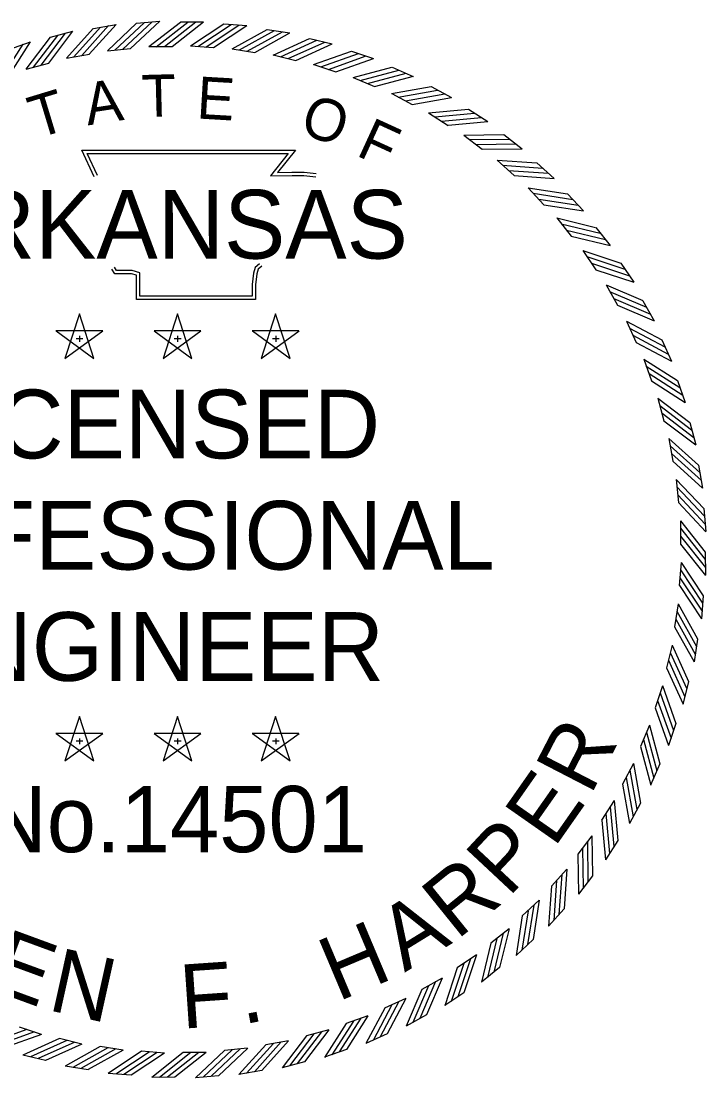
# Model space of a CAD drawing. Extents: x 16 to 1228740, y 11 to 152440.
# Drawn here: x 17.7457 to 17.8572, y 10.8174 to 10.9896 of the extents above; entities that cross this region are included whole.
import ezdxf

# ---------------------------------------------------------------- set-up
doc = ezdxf.new("R2010")
doc.units = 0
doc.layers.add('STAMP_FRED', color=7, linetype='Continuous')

msp = doc.modelspace()

# ---------------------------------------------------------------- linework, layer by layer
at = {"layer": 'STAMP_FRED'}
for p, q in [((17.7645, 10.98923), (17.76826, 10.98957)), ((17.77164, 10.98944), (17.77541, 10.98944)), ((17.75049, 10.98696), (17.75413, 10.98792)), ((17.75745, 10.98838), (17.76116, 10.98904)), ((17.7787, 10.98916), (17.78246, 10.98888)), ((17.78575, 10.98824), (17.78947, 10.98765)), ((17.74366, 10.98497), (17.74722, 10.98623)), ((17.7927, 10.98675), (17.79636, 10.98586)), ((17.75975, 10.98476), (17.76351, 10.98511)), ((17.7665, 10.98543), (17.77028, 10.98543)), ((17.77328, 10.98553), (17.77705, 10.98526)), ((17.78004, 10.98508), (17.78378, 10.98449)), ((17.7995, 10.98468), (17.80308, 10.98349)), ((17.74653, 10.98177), (17.75018, 10.98274)), ((17.75308, 10.98354), (17.7568, 10.9842)), ((17.78675, 10.98407), (17.79042, 10.98317)), ((17.79335, 10.9825), (17.79694, 10.98131)), ((17.80611, 10.98207), (17.80957, 10.98058)), ((17.7998, 10.9804), (17.80327, 10.97892)), ((17.80605, 10.97778), (17.80939, 10.97601)), ((17.81247, 10.97891), (17.81581, 10.97715)), ((17.81206, 10.97464), (17.81525, 10.9726)), ((17.81856, 10.97525), (17.82173, 10.97321)), ((17.8178, 10.97102), (17.8208, 10.96873)), ((17.82432, 10.97109), (17.82732, 10.9688)), ((17.82321, 10.96694), (17.82602, 10.96441)), ((17.82972, 10.96647), (17.83252, 10.96394)), ((17.82827, 10.96242), (17.83086, 10.95967)), ((17.83472, 10.96142), (17.8373, 10.95867)), ((17.83295, 10.95751), (17.83529, 10.95455)), ((17.83929, 10.95597), (17.84163, 10.95302)), ((17.83719, 10.95222), (17.83929, 10.94908)), ((17.84338, 10.95017), (17.84548, 10.94703)), ((17.84099, 10.9466), (17.84282, 10.9433)), ((17.84699, 10.94404), (17.84882, 10.94074)), ((17.75517, 10.94187), (17.75281, 10.93464)), ((17.75752, 10.93464), (17.75517, 10.94188)), ((17.77116, 10.94187), (17.7688, 10.93464)), ((17.77351, 10.93464), (17.77116, 10.94188)), ((17.78715, 10.94187), (17.78479, 10.93464)), ((17.7895, 10.93464), (17.78715, 10.94188)), ((17.84431, 10.94069), (17.84586, 10.93724)), ((17.75897, 10.93911), (17.75136, 10.93912)), ((17.75137, 10.93911), (17.75752, 10.93463)), ((17.75282, 10.93464), (17.75898, 10.93911)), ((17.75463, 10.9379), (17.75576, 10.9379)), ((17.75518, 10.9383), (17.75518, 10.93735)), ((17.77496, 10.93911), (17.76735, 10.93912)), ((17.76736, 10.93911), (17.77351, 10.93463)), ((17.76881, 10.93464), (17.77497, 10.93911)), ((17.77062, 10.9379), (17.77175, 10.9379)), ((17.77117, 10.9383), (17.77117, 10.93735)), ((17.79095, 10.93911), (17.78334, 10.93912)), ((17.78335, 10.93911), (17.7895, 10.93463)), ((17.7848, 10.93464), (17.79096, 10.93911)), ((17.78661, 10.9379), (17.78774, 10.9379)), ((17.78716, 10.9383), (17.78716, 10.93735)), ((17.85008, 10.93764), (17.85163, 10.9342)), ((17.84713, 10.93452), (17.84839, 10.93096)), ((17.85263, 10.93101), (17.85389, 10.92745)), ((17.84943, 10.92814), (17.85039, 10.92449)), ((17.85462, 10.92419), (17.85558, 10.92054)), ((17.8512, 10.9216), (17.85186, 10.91787)), ((17.85604, 10.91723), (17.8567, 10.91351)), ((17.85242, 10.91492), (17.85277, 10.91116)), ((17.85689, 10.91017), (17.85723, 10.90642)), ((17.85309, 10.90818), (17.85312, 10.9044)), ((17.85714, 10.90307), (17.85718, 10.8993)), ((17.85319, 10.90139), (17.85291, 10.89763)), ((17.85682, 10.89597), (17.85654, 10.89221)), ((17.85274, 10.89463), (17.85215, 10.8909)), ((17.85173, 10.88792), (17.85083, 10.88425)), ((17.8559, 10.88892), (17.85531, 10.8852)), ((17.85016, 10.88132), (17.84897, 10.87774)), ((17.85441, 10.88197), (17.85351, 10.87831)), ((17.75517, 10.87631), (17.75281, 10.86907)), ((17.75752, 10.86908), (17.75517, 10.87632)), ((17.77116, 10.87631), (17.7688, 10.86907)), ((17.77351, 10.86908), (17.77116, 10.87632)), ((17.78715, 10.87631), (17.78479, 10.86907)), ((17.7895, 10.86908), (17.78715, 10.87632)), ((17.84806, 10.87488), (17.84658, 10.8714)), ((17.85234, 10.87517), (17.85115, 10.8716)), ((17.75897, 10.87355), (17.75136, 10.87355)), ((17.75137, 10.87355), (17.75752, 10.86907)), ((17.75282, 10.86908), (17.75898, 10.87355)), ((17.75518, 10.87274), (17.75518, 10.87178)), ((17.77496, 10.87355), (17.76735, 10.87355)), ((17.76736, 10.87355), (17.77351, 10.86907)), ((17.76881, 10.86908), (17.77497, 10.87355)), ((17.77117, 10.87274), (17.77117, 10.87178)), ((17.79095, 10.87355), (17.78334, 10.87355)), ((17.78335, 10.87355), (17.7895, 10.86907)), ((17.7848, 10.86908), (17.79096, 10.87355)), ((17.78716, 10.87274), (17.78716, 10.87178)), ((17.75463, 10.87233), (17.75576, 10.87233)), ((17.77062, 10.87233), (17.77175, 10.87233)), ((17.78661, 10.87233), (17.78774, 10.87233)), ((17.84543, 10.86862), (17.84367, 10.86528)), ((17.84973, 10.86857), (17.84824, 10.8651)), ((17.8423, 10.86261), (17.84026, 10.85943)), ((17.84657, 10.8622), (17.84481, 10.85887)), ((17.83868, 10.85687), (17.83639, 10.85387)), ((17.8429, 10.85611), (17.84087, 10.85294)), ((17.8346, 10.85146), (17.83207, 10.84866)), ((17.83875, 10.85035), (17.83646, 10.84736)), ((17.83008, 10.8464), (17.82733, 10.84381)), ((17.83413, 10.84495), (17.8316, 10.84216)), ((17.82517, 10.84173), (17.82221, 10.83938)), ((17.82908, 10.83995), (17.82633, 10.83737)), ((17.81988, 10.83748), (17.81674, 10.83538)), ((17.82363, 10.83539), (17.82068, 10.83305)), ((17.81426, 10.83368), (17.81096, 10.83185)), ((17.81782, 10.83129), (17.81469, 10.8292)), ((17.80835, 10.83036), (17.8049, 10.82881)), ((17.8117, 10.82768), (17.8084, 10.82586)), ((17.80218, 10.82754), (17.79862, 10.82628)), ((17.74898, 10.82451), (17.7454, 10.8257)), ((17.7958, 10.82524), (17.79215, 10.82428)), ((17.8053, 10.82459), (17.80186, 10.82305)), ((17.75558, 10.82295), (17.75191, 10.82384)), ((17.76229, 10.82194), (17.75856, 10.82252)), ((17.78925, 10.82347), (17.78553, 10.82282)), ((17.74963, 10.82027), (17.74597, 10.82116)), ((17.76905, 10.82148), (17.76529, 10.82176)), ((17.77583, 10.82159), (17.77206, 10.82155)), ((17.78258, 10.82225), (17.77882, 10.82191)), ((17.79867, 10.82204), (17.79511, 10.82079)), ((17.75658, 10.81877), (17.75286, 10.81936)), ((17.79185, 10.82005), (17.7882, 10.81909)), ((17.76363, 10.81786), (17.75987, 10.81813)), ((17.77073, 10.81753), (17.76696, 10.81749)), ((17.77783, 10.81779), (17.77408, 10.81744)), ((17.78489, 10.81863), (17.78117, 10.81797))]:
    msp.add_line(p, q, dxfattribs=at)
for points in [[(17.76226, 10.98501), (17.76701, 10.98947)], [(17.76351, 10.98511), (17.76826, 10.98958)], [(17.76649, 10.98542), (17.77164, 10.98943)], [(17.76771, 10.98541), (17.77285, 10.98942)], [(17.76902, 10.98544), (17.77416, 10.98945)], [(17.77027, 10.98543), (17.77542, 10.98944)], [(17.75018, 10.98274), (17.75413, 10.98792)], [(17.75307, 10.98354), (17.75744, 10.98838)], [(17.75427, 10.98374), (17.75864, 10.98858)], [(17.75556, 10.98399), (17.75992, 10.98884)], [(17.75679, 10.9842), (17.76116, 10.98904)], [(17.75974, 10.98476), (17.7645, 10.98922)], [(17.76095, 10.98486), (17.76571, 10.98932)], [(17.77327, 10.98553), (17.7787, 10.98915)], [(17.77448, 10.98543), (17.77991, 10.98905)], [(17.77579, 10.98536), (17.78122, 10.98898)], [(17.77704, 10.98526), (17.78247, 10.98888)], [(17.78004, 10.98508), (17.78574, 10.98824)], [(17.78124, 10.98488), (17.78694, 10.98804)], [(17.78253, 10.9847), (17.78824, 10.98786)], [(17.74371, 10.98073), (17.74722, 10.98623)], [(17.74653, 10.98177), (17.75048, 10.98696)], [(17.7477, 10.98207), (17.75166, 10.98726)], [(17.74896, 10.98243), (17.75292, 10.98762)], [(17.78377, 10.98449), (17.78948, 10.98766)], [(17.78675, 10.98406), (17.79269, 10.98674)], [(17.78792, 10.98377), (17.79387, 10.98645)], [(17.7892, 10.98348), (17.79515, 10.98617)], [(17.74252, 10.98033), (17.74603, 10.98582)], [(17.79042, 10.98318), (17.79636, 10.98586)], [(17.79334, 10.9825), (17.79949, 10.98468)], [(17.79449, 10.98211), (17.80064, 10.98429)], [(17.79574, 10.98172), (17.80189, 10.9839)], [(17.79693, 10.98131), (17.80308, 10.98349)], [(17.79979, 10.9804), (17.8061, 10.98207)], [(17.8009, 10.97991), (17.80721, 10.98158)], [(17.80212, 10.97942), (17.80843, 10.98109)], [(17.80327, 10.97892), (17.80958, 10.98059)], [(17.80604, 10.97777), (17.81247, 10.97891)], [(17.80711, 10.9772), (17.81353, 10.97834)], [(17.80828, 10.97661), (17.81471, 10.97775)], [(17.80939, 10.97601), (17.81581, 10.97715)], [(17.81206, 10.97464), (17.81855, 10.97525)], [(17.81307, 10.97398), (17.81957, 10.97458)], [(17.81419, 10.97329), (17.82069, 10.9739)], [(17.81524, 10.97261), (17.82174, 10.97321)], [(17.81779, 10.97102), (17.82432, 10.97109)], [(17.81875, 10.97028), (17.82527, 10.97034)], [(17.81981, 10.9695), (17.82633, 10.96957)], [(17.8208, 10.96873), (17.82732, 10.9688)], [(17.7576, 10.96421), (17.75559, 10.96856), (17.79036, 10.96858), (17.78745, 10.96493), (17.78981, 10.96496), (17.79179, 10.96499), (17.79376, 10.96477)], [(17.7581, 10.96444), (17.75645, 10.96801), (17.78921, 10.96803), (17.7863, 10.96436), (17.78982, 10.96441), (17.79176, 10.96443), (17.7937, 10.96422)], [(17.82321, 10.96694), (17.82971, 10.96647)], [(17.8241, 10.96612), (17.83061, 10.96565)], [(17.82509, 10.96526), (17.8316, 10.96479)], [(17.82602, 10.96441), (17.83252, 10.96394)], [(17.82827, 10.96243), (17.83471, 10.96142)], [(17.82909, 10.96153), (17.83554, 10.96052)], [(17.83001, 10.9606), (17.83645, 10.95959)], [(17.83086, 10.95967), (17.8373, 10.95867)], [(17.83294, 10.95751), (17.83928, 10.95597)], [(17.83368, 10.95655), (17.84002, 10.95501)], [(17.83452, 10.95554), (17.84086, 10.95401)], [(17.83529, 10.95455), (17.84163, 10.95302)], [(17.83719, 10.95222), (17.84338, 10.95017)], [(17.78453, 10.95006), (17.7838, 10.94947), (17.78354, 10.94854), (17.78334, 10.94666), (17.78334, 10.94478), (17.76503, 10.94478), (17.76503, 10.94747), (17.76503, 10.9486), (17.76378, 10.94898), (17.76123, 10.94898), (17.7609, 10.94948)], [(17.83785, 10.95121), (17.84404, 10.94915)], [(17.8386, 10.95013), (17.84479, 10.94808)], [(17.78488, 10.94964), (17.78428, 10.94915), (17.78409, 10.94843), (17.78389, 10.94663), (17.78389, 10.94423), (17.76448, 10.94423), (17.76448, 10.94747), (17.76448, 10.94819), (17.76369, 10.94843), (17.76093, 10.94843), (17.76044, 10.94918)], [(17.83929, 10.94908), (17.84548, 10.94703)], [(17.84099, 10.9466), (17.84699, 10.94405)], [(17.84156, 10.94554), (17.84756, 10.94298)], [(17.84222, 10.94441), (17.84822, 10.94185)], [(17.84282, 10.9433), (17.84882, 10.94074)], [(17.84431, 10.94069), (17.85007, 10.93765)], [(17.84479, 10.93958), (17.85056, 10.93653)], [(17.84536, 10.9384), (17.85112, 10.93535)], [(17.84586, 10.93725), (17.85163, 10.9342)], [(17.84713, 10.93452), (17.85262, 10.93101)], [(17.84752, 10.93338), (17.85302, 10.92987)], [(17.84798, 10.93215), (17.85348, 10.92864)], [(17.84839, 10.93096), (17.85389, 10.92745)], [(17.84943, 10.92815), (17.85462, 10.92419)], [(17.84973, 10.92697), (17.85491, 10.92302)], [(17.85009, 10.92571), (17.85528, 10.92176)], [(17.8504, 10.92449), (17.85558, 10.92054)], [(17.8512, 10.9216), (17.85604, 10.91723)], [(17.8514, 10.9204), (17.85624, 10.91603)], [(17.85165, 10.91912), (17.8565, 10.91475)], [(17.85186, 10.91788), (17.8567, 10.91351)], [(17.85242, 10.91493), (17.85688, 10.91017)], [(17.85252, 10.91372), (17.85698, 10.90897)], [(17.85267, 10.91242), (17.85713, 10.90766)], [(17.85277, 10.91117), (17.85724, 10.90641)], [(17.85308, 10.90818), (17.85714, 10.90307)], [(17.85308, 10.90697), (17.85714, 10.90186)], [(17.85312, 10.90566), (17.85718, 10.90055)], [(17.85312, 10.9044), (17.85718, 10.89929)], [(17.85309, 10.90019), (17.85671, 10.89477)], [(17.85319, 10.9014), (17.85681, 10.89598)], [(17.85302, 10.89888), (17.85664, 10.89346)], [(17.85292, 10.89763), (17.85654, 10.89221)], [(17.85253, 10.89344), (17.8557, 10.88773)], [(17.85273, 10.89463), (17.8559, 10.88893)], [(17.85236, 10.89214), (17.85552, 10.88643)], [(17.85215, 10.8909), (17.85532, 10.88519)], [(17.85172, 10.88793), (17.8544, 10.88198)], [(17.85143, 10.88675), (17.85411, 10.8808)], [(17.85114, 10.88547), (17.85382, 10.87953)], [(17.85084, 10.88425), (17.85352, 10.87831)], [(17.85016, 10.88133), (17.85234, 10.87518)], [(17.84977, 10.88018), (17.85195, 10.87403)], [(17.84897, 10.87774), (17.85115, 10.87159)], [(17.84938, 10.87893), (17.85156, 10.87278)], [(17.84806, 10.87488), (17.84973, 10.86857)], [(17.84708, 10.87255), (17.84875, 10.86625)], [(17.84757, 10.87377), (17.84924, 10.86746)], [(17.84658, 10.8714), (17.84825, 10.8651)], [(17.84486, 10.86756), (17.846, 10.86114)], [(17.84543, 10.86863), (17.84657, 10.86221)], [(17.84427, 10.86639), (17.84541, 10.85997)], [(17.84367, 10.86529), (17.84481, 10.85886)], [(17.8423, 10.86261), (17.8429, 10.85612)], [(17.84095, 10.86048), (17.84156, 10.85399)], [(17.84164, 10.8616), (17.84224, 10.8551)], [(17.84027, 10.85943), (17.84087, 10.85293)], [(17.83868, 10.85688), (17.83875, 10.85036)], [(17.83793, 10.85592), (17.838, 10.8494)], [(17.83639, 10.85387), (17.83646, 10.84735)], [(17.83716, 10.85486), (17.83723, 10.84834)], [(17.83378, 10.85057), (17.8333, 10.84407)], [(17.8346, 10.85146), (17.83413, 10.84496)], [(17.83207, 10.84866), (17.8316, 10.84215)], [(17.83292, 10.84958), (17.83245, 10.84307)], [(17.82919, 10.84558), (17.82818, 10.83914)], [(17.83008, 10.8464), (17.82908, 10.83996)], [(17.82733, 10.84381), (17.82632, 10.83737)], [(17.82826, 10.84467), (17.82725, 10.83822)], [(17.82517, 10.84173), (17.82363, 10.83539)], [(17.8232, 10.84015), (17.82167, 10.83381)], [(17.82421, 10.84099), (17.82267, 10.83465)], [(17.82221, 10.83938), (17.82067, 10.83304)], [(17.81887, 10.83682), (17.81681, 10.83063)], [(17.81988, 10.83749), (17.81783, 10.83129)], [(17.81674, 10.83538), (17.81469, 10.82919)], [(17.81779, 10.83607), (17.81574, 10.82988)], [(17.8132, 10.83311), (17.81064, 10.82711)], [(17.81426, 10.83369), (17.8117, 10.82769)], [(17.81096, 10.83185), (17.8084, 10.82585)], [(17.81207, 10.83245), (17.80951, 10.82645)], [(17.80724, 10.82988), (17.80419, 10.82411)], [(17.80835, 10.83037), (17.80531, 10.8246)], [(17.80491, 10.82881), (17.80186, 10.82304)], [(17.80606, 10.82932), (17.80301, 10.82355)], [(17.79862, 10.82628), (17.79511, 10.82078)], [(17.79981, 10.82669), (17.7963, 10.82119)], [(17.80104, 10.82715), (17.79752, 10.82166)], [(17.80218, 10.82755), (17.79867, 10.82205)], [(17.74659, 10.82529), (17.74044, 10.82311)], [(17.74784, 10.82491), (17.74169, 10.82272)], [(17.74899, 10.82451), (17.74284, 10.82233)], [(17.79215, 10.82428), (17.7882, 10.81909)], [(17.79337, 10.82459), (17.78942, 10.8194)], [(17.79463, 10.82495), (17.79068, 10.81976)], [(17.79581, 10.82524), (17.79185, 10.82006)], [(17.75191, 10.82384), (17.74597, 10.82116)], [(17.75313, 10.82353), (17.74719, 10.82085)], [(17.75441, 10.82325), (17.74846, 10.82057)], [(17.75559, 10.82295), (17.74964, 10.82027)], [(17.75856, 10.82252), (17.75285, 10.81936)], [(17.78554, 10.82281), (17.78117, 10.81797)], [(17.78678, 10.82302), (17.78241, 10.81818)], [(17.78806, 10.82328), (17.78369, 10.81843)], [(17.78926, 10.82348), (17.78489, 10.81863)], [(17.7598, 10.82231), (17.75409, 10.81915)], [(17.7611, 10.82214), (17.75539, 10.81898)], [(17.76229, 10.82194), (17.75659, 10.81878)], [(17.76529, 10.82176), (17.75987, 10.81813)], [(17.76654, 10.82165), (17.76112, 10.81803)], [(17.76785, 10.82158), (17.76243, 10.81796)], [(17.76906, 10.82148), (17.76363, 10.81786)], [(17.77206, 10.82155), (17.76695, 10.81749)], [(17.77332, 10.82155), (17.76821, 10.81749)], [(17.77463, 10.82159), (17.76952, 10.81753)], [(17.77584, 10.82159), (17.77073, 10.81753)], [(17.77883, 10.8219), (17.77407, 10.81744)], [(17.78008, 10.82201), (17.77532, 10.81754)], [(17.78138, 10.82216), (17.77662, 10.81769)], [(17.78259, 10.82226), (17.77783, 10.81779)]]:
    msp.add_lwpolyline(points, dxfattribs=at)

# ---------------------------------------------------------------- texts
for s, height, rotation, p in [('T', 0.00686, 1.4789, (17.76539, 10.97394)), ('A', 0.00686, 8.6788, (17.75654, 10.97258)), ('E', 0.00686, 356.672, (17.77417, 10.97373)), ('T', 0.00686, 16.9015, (17.74821, 10.9704)), ('O', 0.00686, 341.2218, (17.79082, 10.97138)), ('F', 0.00686, 335.3628, (17.80007, 10.96777)), ('R', 0.01042, 62.6418, (17.83844, 10.86329)), ('E', 0.01042, 54.981, (17.83249, 10.85473)), ('P', 0.01042, 46.9554, (17.82508, 10.8467)), ('R', 0.01042, 38.9298, (17.81663, 10.83978)), ('A', 0.01042, 31.6338, (17.80817, 10.83457)), ('E', 0.01042, 339.8321, (17.74002, 10.83208)), ('H', 0.01042, 22.8786, (17.79725, 10.82979)), ('N', 0.01042, 347.4929, (17.74982, 10.82852)), ('F', 0.01042, 3.9089, (17.77189, 10.82544)), ('.', 0.01042, 11.205, (17.7818, 10.82611))]:
    msp.add_text(s, height=height, rotation=rotation, dxfattribs=at).set_placement(p)
for s, height, p in [('ARKANSAS', 0.011193, (17.72717, 10.95089)), ('LICENSED', 0.011193, (17.7293, 10.91835)), ('PROFESSIONAL', 0.0111934, (17.70638, 10.90023)), ('ENGINEER', 0.011193, (17.72663, 10.88211)), ('No.14501', 0.010794, (17.73943, 10.8542))]:
    msp.add_text(s, height=height, dxfattribs=at).set_placement(p)

doc.saveas('drawing.dxf')
